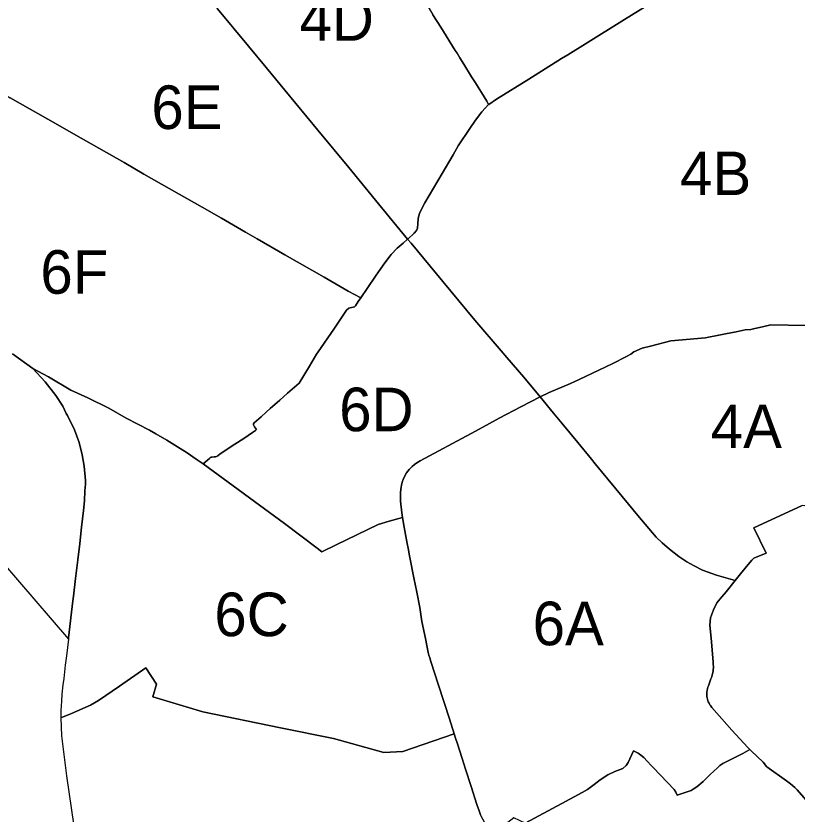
# Model space of a CAD drawing. Extents: x 152750 to 166250, y 378996 to 390000.
# Drawn here: x 157492 to 161080, y 382624 to 386288 of the extents above; entities that cross this region are included whole.
import ezdxf

# ---------------------------------------------------------------- set-up
doc = ezdxf.new("R2010")
doc.units = 0
doc.layers.add('BLT_Nummers', color=7, linetype='Continuous')
doc.layers.add('BLT_Shapes', color=7, linetype='Continuous')

msp = doc.modelspace()

# ---------------------------------------------------------------- linework, layer by layer
at = {"layer": 'BLT_Shapes'}
for p, q in [((158559.6, 386149.1), (158417.7, 386321.3)), ((159998.4, 386092.3), (160026.6, 386109.9)), ((159847.6, 385998.4), (159998.4, 386092.3)), ((159548.7, 386066.7), (159585, 386008.8)), ((159699.8, 385906.1), (159847.6, 385998.4)), ((159630.8, 385936.3), (159654.8, 385896.4)), ((159654.8, 385896.4), (159662.6, 385881.4)), ((159663.3, 385882.1), (159699.8, 385906.1)), ((159647.7, 385865.1), (159662.6, 385881.4)), ((159662.6, 385881.4), (159663.3, 385882.1)), ((159499.5, 385650), (159523.9, 385691.3)), ((159449.8, 385565.1), (159499.5, 385650)), ((159157.3, 385425.3), (159020.3, 385592.2)), ((159291.1, 385263.1), (159157.3, 385425.3)), ((159341.3, 385365.9), (159347.2, 385385.4)), ((159337.9, 385334.7), (159339.4, 385354.5)), ((159339.4, 385354.5), (159341.3, 385365.9)), ((159321.3, 385290.2), (159331.4, 385303.2)), ((159331.4, 385303.2), (159335.6, 385313.6)), ((159335.6, 385313.6), (159337.9, 385334.7)), ((159291.1, 385263.1), (159291.3, 385263.2)), ((159306.7, 385244.2), (159291.1, 385263.1)), ((159291.3, 385263.2), (159321.3, 385290.2)), ((159452, 385068.7), (159306.7, 385244.2)), ((158907.8, 385088.8), (158727.5, 385191.8)), ((159186.1, 385154.7), (159214.8, 385192.1)), ((159214.8, 385192.1), (159242.2, 385222.2)), ((159018.5, 385024.9), (158907.8, 385088.8)), ((159075.5, 384993.5), (159018.5, 385024.9)), ((159050.9, 384956.8), (159064, 384976.7)), ((159064, 384976.7), (159075.5, 384993.5)), ((159046.4, 384952.7), (159050.9, 384956.8)), ((160500.2, 384796.8), (160658.9, 384809.4)), ((160330.8, 384745.2), (160367.7, 384763.2)), ((157568.7, 384669.9), (157476.5, 384736.7)), ((158872.5, 384734.7), (158880.6, 384745.9)), ((159824.2, 384630.2), (159747, 384719.9)), ((157568.7, 384669.9), (157641, 384630.6)), ((157625.3, 384607.9), (157568.7, 384669.9)), ((157641, 384630.6), (157743.5, 384569.9)), ((159900, 384538.8), (159824.2, 384630.2)), ((160039.7, 384600.3), (160079.6, 384619)), ((157743.5, 384569.9), (157821.2, 384534.1)), ((158704.3, 384523.5), (158739.8, 384555.6)), ((159811.6, 384493.4), (159900, 384538.8)), ((159900, 384538.8), (159900.2, 384538.9)), ((157723, 384462.6), (157706.7, 384496.4)), ((158617.5, 384447.1), (158641.7, 384468.3)), ((158583, 384415.5), (158586.2, 384419.7)), ((158586.2, 384419.7), (158617.5, 384447.1)), ((157781.6, 384329), (157761, 384388.2)), ((158578.9, 384375.6), (158591.4, 384384)), ((158596.7, 384388.8), (158588.1, 384402.2)), ((158591.4, 384384), (158596.7, 384388.8)), ((158134.5, 384370.1), (158184.3, 384340.8)), ((158497.4, 384321.5), (158537.9, 384348.3)), ((158537.9, 384348.3), (158578.9, 384375.6)), ((158184.3, 384340.8), (158245.9, 384302.4)), ((158430.6, 384277), (158497.4, 384321.5)), ((158245.9, 384302.4), (158278, 384281.6)), ((158278, 384281.6), (158320.3, 384253.7)), ((158320.3, 384253.7), (158352.5, 384231.8)), ((158352.5, 384231.8), (158371.5, 384249.1)), ((158386.5, 384261.5), (158392.3, 384263)), ((159322.4, 384228.7), (159333, 384236.8)), ((158352.5, 384231.8), (158725.7, 383957.6)), ((159270.1, 384159.2), (159277.4, 384176.1)), ((159277.4, 384176.1), (159286.5, 384190.3)), ((157808.9, 384108.2), (157811.2, 384137.7)), ((157811.2, 384137.7), (157811.6, 384154.5)), ((159261.2, 384123.8), (159263, 384133.9)), ((159258.4, 384085.6), (159259, 384101.8)), ((159259, 384101.8), (159261.2, 384123.8)), ((159259, 384060.6), (159258.4, 384085.6)), ((160881.5, 383937.4), (161102.9, 384039.9)), ((159267.9, 383985.6), (159206.9, 383968.8)), ((159206.9, 383968.8), (159267.9, 383985.6)), ((159275.4, 383940.8), (159267.9, 383985.6)), ((160398.6, 383934.1), (160348.6, 383994.7)), ((158725.7, 383957.6), (158875.7, 383844)), ((160433.3, 383895.4), (160398.6, 383934.1)), ((160937.5, 383821.9), (160881.5, 383937.4)), ((158875.7, 383844), (158897.1, 383827.1)), ((159321, 383701), (159300.3, 383809)), ((160872.6, 383789.9), (160882, 383798)), ((160882, 383798), (160937.5, 383821.9)), ((160646.2, 383743.9), (160606.6, 383764)), ((160862.7, 383779.3), (160872.6, 383789.9)), ((160710.4, 383719.8), (160646.2, 383743.9)), ((159325.2, 383678.4), (159321, 383701)), ((160795.2, 383696.3), (160710.4, 383719.8)), ((160711.4, 383593.9), (160734.5, 383620.9)), ((159355.7, 383507.5), (159346.4, 383572.2)), ((159373.4, 383430.4), (159355.7, 383507.5)), ((159379.6, 383398.3), (159373.4, 383430.4)), ((159392.6, 383340.9), (159389.1, 383352.5)), ((159397.9, 383323.7), (159392.6, 383340.9)), ((159432.8, 383214.7), (159397.9, 383323.7)), ((158088.2, 383294.8), (158136.8, 383219.8)), ((158136.8, 383219.8), (158120.7, 383162.5)), ((160665.2, 383177.2), (160665.6, 383185.1)), ((160665.2, 383170.5), (160665.2, 383177.2)), ((158120.7, 383162.5), (158350.9, 383093.6)), ((160667.9, 383151.1), (160666.7, 383157.9)), ((160669.9, 383144.7), (160667.9, 383151.1)), ((160672.3, 383139.1), (160669.9, 383144.7)), ((159268.3, 382911.5), (159504.8, 382992)), ((160868.5, 382914.2), (160863.3, 382919.8)), ((159556.6, 382830.2), (159541.6, 382879)), ((160648.3, 382773.8), (160619.1, 382749)), ((160602.7, 382738.1), (160593.4, 382732.2)), ((160619.1, 382749), (160602.7, 382738.1)), ((161069.1, 382746.3), (161050.5, 382762))]:
    msp.add_line(p, q, dxfattribs=at)
for points in [[(158206.4, 386577.5), (158296.1, 386469.4), (158417.7, 386321.3), (158559.6, 386149.1), (158640.6, 386051.2), (158726.9, 385947.1), (158878.9, 385763.5), (159020.3, 385592.2), (159157.3, 385425.3), (159291.1, 385263.1)], [(160613.2, 386488.3), (160580.8, 386461.3), (160520.7, 386417.7), (160286.8, 386271.8), (160108.2, 386160.3), (160026.6, 386109.9), (159998.4, 386092.3), (159847.6, 385998.4), (159699.8, 385906.1), (159663.3, 385882.1), (159662.6, 385881.4)], [(160286.8, 386271.8), (160520.7, 386417.7), (160580.8, 386461.3), (160613.2, 386488.3)], [(159299.6, 386466.5), (159339, 386403.1), (159389.6, 386322.5), (159407.4, 386293.5), (159442.8, 386236.3), (159509.8, 386129.4), (159517.9, 386116.7)], [(159662.6, 385881.4), (159654.8, 385896.4), (159630.8, 385936.3), (159614.8, 385961), (159602.5, 385980.9), (159585, 386008.8), (159548.7, 386066.7), (159530.9, 386095.3), (159517.9, 386116.7), (159509.8, 386129.4), (159442.8, 386236.3), (159407.4, 386293.5)], [(160026.6, 386109.9), (160108.2, 386160.3), (160286.8, 386271.8)], [(158726.9, 385947.1), (158640.6, 386051.2), (158559.6, 386149.1)], [(159517.9, 386116.7), (159530.9, 386095.3), (159548.7, 386066.7)], [(157147.5, 386096.8), (157264.2, 386027.4), (157403.9, 385947.6), (157465.3, 385912.5), (157684.2, 385787.5), (157756.2, 385746.7), (157988.5, 385614.5), (158079.9, 385562), (158276, 385450.2), (158347.1, 385409.7), (158435.6, 385358.9), (158545.8, 385295.9), (158599.5, 385264.6), (158727.5, 385191.8), (158907.8, 385088.8), (159018.5, 385024.9), (159075.5, 384993.5)], [(159585, 386008.8), (159602.5, 385980.9), (159614.8, 385961), (159630.8, 385936.3)], [(159020.3, 385592.2), (158878.9, 385763.5), (158726.9, 385947.1)], [(157756.2, 385746.7), (157684.2, 385787.5), (157465.3, 385912.5)], [(159662.6, 385881.4), (159647.7, 385865.1), (159631.4, 385847.3), (159602.5, 385809.6), (159576.2, 385771.2), (159523.9, 385691.3), (159499.5, 385650), (159449.8, 385565.1), (159370.6, 385429.9), (159347.2, 385385.4), (159341.3, 385365.9), (159339.4, 385354.5), (159337.9, 385334.7), (159335.6, 385313.6), (159331.4, 385303.2), (159321.3, 385290.2), (159291.3, 385263.2), (159291.1, 385263.1)], [(159523.9, 385691.3), (159576.2, 385771.2), (159602.5, 385809.6), (159631.4, 385847.3), (159647.7, 385865.1)], [(158276, 385450.2), (158079.9, 385562), (157988.5, 385614.5), (157756.2, 385746.7)], [(159347.2, 385385.4), (159370.6, 385429.9), (159449.8, 385565.1)], [(158435.6, 385358.9), (158347.1, 385409.7), (158276, 385450.2)], [(158727.5, 385191.8), (158599.5, 385264.6), (158545.8, 385295.9), (158435.6, 385358.9)], [(159291.1, 385263.1), (159269.8, 385245.1), (159242.2, 385222.2), (159214.8, 385192.1), (159186.1, 385154.7), (159146.5, 385097.5), (159104.7, 385036.4), (159075.5, 384993.5)], [(159242.2, 385222.2), (159269.8, 385245.1), (159291.1, 385263.1)], [(159291.1, 385263.1), (159306.7, 385244.2), (159452, 385068.7), (159599.6, 384891.3), (159720.3, 384751.2), (159747, 384719.9), (159824.2, 384630.2), (159900, 384538.8)], [(159075.5, 384993.5), (159104.7, 385036.4), (159146.5, 385097.5), (159186.1, 385154.7)], [(159747, 384719.9), (159720.3, 384751.2), (159599.6, 384891.3), (159452, 385068.7)], [(159075.5, 384993.5), (159064, 384976.7), (159050.9, 384956.8), (159046.4, 384952.7), (159027.4, 384947.6), (159020.5, 384946), (159010.8, 384937.3), (159003.6, 384928.1), (158951.4, 384850.5), (158880.6, 384745.9), (158872.5, 384734.7), (158839.9, 384680.1), (158792.8, 384602.5), (158739.8, 384555.6), (158704.3, 384523.5), (158660.1, 384485), (158641.7, 384468.3), (158617.5, 384447.1), (158586.2, 384419.7), (158583, 384415.5), (158582.8, 384410.8), (158588.1, 384402.2), (158596.7, 384388.8), (158591.4, 384384), (158578.9, 384375.6), (158537.9, 384348.3), (158497.4, 384321.5), (158430.6, 384277), (158418.6, 384268), (158413.2, 384265.2), (158407.7, 384264.3), (158401.7, 384263.4), (158392.3, 384263), (158386.5, 384261.5), (158381.8, 384258.3), (158371.5, 384249.1), (158352.5, 384231.8)], [(158880.6, 384745.9), (158951.4, 384850.5), (159003.6, 384928.1), (159010.8, 384937.3), (159020.5, 384946)], [(159020.5, 384946), (159027.4, 384947.6), (159046.4, 384952.7)], [(161120.2, 384867.2), (160958.7, 384869.5), (160952.6, 384868.2), (160907.9, 384858.1), (160886.6, 384852.9), (160867.1, 384848.9), (160841.6, 384847.2), (160800.8, 384838), (160751.9, 384828.9), (160704.6, 384818.6), (160673.7, 384812.5), (160658.9, 384809.4), (160500.2, 384796.8), (160406.1, 384772.5), (160367.7, 384763.2), (160330.8, 384745.2), (160316.1, 384735.1), (160294.1, 384722.4), (160234.2, 384692.6), (160168.6, 384661), (160079.6, 384619), (160039.7, 384600.3), (159941.4, 384558.4), (159900.2, 384538.9), (159900, 384538.8)], [(160886.6, 384852.9), (160907.9, 384858.1), (160952.6, 384868.2), (160958.7, 384869.5), (161120.2, 384867.2), (161149.4, 384865.5)], [(160704.6, 384818.6), (160751.9, 384828.9), (160800.8, 384838)], [(160800.8, 384838), (160841.6, 384847.2), (160867.1, 384848.9), (160886.6, 384852.9)], [(160367.7, 384763.2), (160406.1, 384772.5), (160500.2, 384796.8)], [(160658.9, 384809.4), (160673.7, 384812.5), (160704.6, 384818.6)], [(157476.5, 384736.7), (157568.7, 384669.9)], [(158739.8, 384555.6), (158792.8, 384602.5), (158839.9, 384680.1), (158872.5, 384734.7)], [(160079.6, 384619), (160168.6, 384661), (160234.2, 384692.6), (160294.1, 384722.4), (160316.1, 384735.1), (160330.8, 384745.2)], [(158352.5, 384231.8), (158320.3, 384253.7), (158278, 384281.6), (158245.9, 384302.4), (158184.3, 384340.8), (158134.5, 384370.1), (158105.5, 384386.4), (157997.9, 384441.2), (157918, 384487), (157821.2, 384534.1), (157743.5, 384569.9), (157641, 384630.6), (157568.7, 384669.9)], [(157568.7, 384669.9), (157625.3, 384607.9), (157674.4, 384546.1), (157706.7, 384496.4), (157723, 384462.6), (157728, 384453.4), (157761, 384388.2), (157781.6, 384329), (157796.2, 384273.2), (157805.4, 384220.4), (157811.6, 384154.5), (157811.2, 384137.7), (157808.9, 384108.2), (157805.9, 384062.1), (157801.7, 384017.2), (157797.8, 383979.3), (157793.6, 383940.2), (157784.9, 383865.4), (157776.3, 383791.2), (157765.7, 383705.3), (157755.9, 383624.1), (157753.4, 383602.6), (157733.6, 383433.2), (157732.8, 383426.7)], [(157706.7, 384496.4), (157674.4, 384546.1), (157625.3, 384607.9)], [(159900.2, 384538.9), (159941.4, 384558.4), (160039.7, 384600.3)], [(157821.2, 384534.1), (157918, 384487), (157997.9, 384441.2)], [(159900, 384538.8), (159811.6, 384493.4), (159711.9, 384440.8), (159653, 384409.5), (159582.5, 384371.3), (159348, 384245.4), (159333, 384236.8), (159322.4, 384228.7), (159312.3, 384219.9), (159297.6, 384205.5), (159286.5, 384190.3), (159277.4, 384176.1), (159270.1, 384159.2), (159266.3, 384148.1), (159263, 384133.9), (159261.2, 384123.8), (159259, 384101.8), (159258.4, 384085.6), (159259, 384060.6), (159264.3, 384007.3), (159267.9, 383985.6)], [(159900, 384538.8), (159961.6, 384464.6), (159998.9, 384418.8), (160072.1, 384329.8), (160135.2, 384253.5), (160152.7, 384231.6), (160305.6, 384046.9), (160348.6, 383994.7), (160398.6, 383934.1), (160433.3, 383895.4), (160459.5, 383869.5), (160493.8, 383839.6), (160536.2, 383806.7), (160573.7, 383782.3), (160606.6, 383764), (160646.2, 383743.9), (160710.4, 383719.8), (160795.2, 383696.3)], [(159998.9, 384418.8), (159961.6, 384464.6), (159900, 384538.8)], [(158641.7, 384468.3), (158660.1, 384485), (158704.3, 384523.5)], [(159582.5, 384371.3), (159653, 384409.5), (159711.9, 384440.8), (159811.6, 384493.4)], [(157761, 384388.2), (157728, 384453.4), (157723, 384462.6)], [(157997.9, 384441.2), (158105.5, 384386.4), (158134.5, 384370.1)], [(158588.1, 384402.2), (158582.8, 384410.8), (158583, 384415.5)], [(160135.2, 384253.5), (160072.1, 384329.8), (159998.9, 384418.8)], [(159333, 384236.8), (159348, 384245.4), (159582.5, 384371.3)], [(157811.6, 384154.5), (157805.4, 384220.4), (157796.2, 384273.2), (157781.6, 384329)], [(158392.3, 384263), (158401.7, 384263.4), (158407.7, 384264.3), (158413.2, 384265.2), (158418.6, 384268), (158430.6, 384277)], [(158371.5, 384249.1), (158381.8, 384258.3), (158386.5, 384261.5)], [(160348.6, 383994.7), (160305.6, 384046.9), (160152.7, 384231.6), (160135.2, 384253.5)], [(159206.9, 383968.8), (159155.5, 383952.7), (158962.9, 383859.8), (158897.1, 383827.1), (158875.7, 383844), (158725.7, 383957.6), (158352.5, 384231.8)], [(159286.5, 384190.3), (159297.6, 384205.5), (159312.3, 384219.9), (159322.4, 384228.7)], [(159263, 384133.9), (159266.3, 384148.1), (159270.1, 384159.2)], [(161492.7, 384141), (161232.4, 384136.5), (161220.8, 384025.3), (161102.9, 384039.9), (160881.5, 383937.4), (160937.5, 383821.9)], [(157801.7, 384017.2), (157805.9, 384062.1), (157808.9, 384108.2)], [(159267.9, 383985.6), (159264.3, 384007.3), (159259, 384060.6)], [(157793.6, 383940.2), (157797.8, 383979.3), (157801.7, 384017.2)], [(159267.9, 383985.6), (159275.4, 383940.8), (159289.5, 383865.2), (159293.6, 383843.7), (159300.3, 383809), (159321, 383701), (159325.2, 383678.4), (159333.5, 383642.2), (159346.4, 383572.2), (159355.7, 383507.5), (159373.4, 383430.4), (159379.6, 383398.3)], [(158897.1, 383827.1), (158962.9, 383859.8), (159155.5, 383952.7), (159206.9, 383968.8)], [(157776.3, 383791.2), (157784.9, 383865.4), (157793.6, 383940.2)], [(159300.3, 383809), (159293.6, 383843.7), (159289.5, 383865.2), (159275.4, 383940.8)], [(160493.8, 383839.6), (160459.5, 383869.5), (160433.3, 383895.4)], [(160606.6, 383764), (160573.7, 383782.3), (160536.2, 383806.7), (160493.8, 383839.6)], [(157397.8, 383816.1), (157498.7, 383699.6), (157732.8, 383426.7), (157723.2, 383349.5), (157718.2, 383307.9), (157711.3, 383246), (157707.4, 383216.4), (157703.2, 383174.8), (157700.5, 383141.4), (157697.9, 383099.2), (157697.9, 383065.1), (157701.5, 382982.9), (157724.5, 382799.2), (157778.7, 382420.6), (157721.2, 382367.1), (157633.4, 382451.6), (157531.2, 382505), (157333.5, 382604.9)], [(157397.8, 383816.1), (157498.7, 383699.6), (157732.8, 383426.7)], [(160937.5, 383821.9), (160882, 383798), (160872.6, 383789.9), (160862.7, 383779.3), (160819.5, 383726.8), (160795.2, 383696.3)], [(157755.9, 383624.1), (157765.7, 383705.3), (157776.3, 383791.2)], [(160795.2, 383696.3), (160819.5, 383726.8), (160862.7, 383779.3)], [(160795.2, 383696.3), (160753.8, 383644.3), (160734.5, 383620.9), (160711.4, 383593.9), (160695.6, 383561.8), (160682.7, 383525.3), (160678.5, 383491.5), (160685.8, 383431.4), (160694.3, 383322.7), (160695.1, 383311.9), (160696.4, 383300.1), (160694.2, 383283.3), (160692.4, 383272.1), (160690.4, 383262.6), (160688, 383253.5), (160684.5, 383244), (160679.2, 383230.3), (160672.5, 383212.6), (160669.8, 383205.5), (160667.9, 383199.5), (160666.5, 383190.5), (160665.6, 383185.1), (160665.2, 383177.2), (160665.2, 383170.5), (160665.6, 383164.1), (160666.7, 383157.9), (160667.9, 383151.1), (160669.9, 383144.7), (160672.3, 383139.1), (160675.4, 383132.1), (160679.4, 383125.2), (160681.9, 383121.4), (160688.5, 383112.2), (160780, 383008.5), (160853.9, 382929.9), (160863.3, 382919.8)], [(160734.5, 383620.9), (160753.8, 383644.3), (160795.2, 383696.3)], [(159346.4, 383572.2), (159333.5, 383642.2), (159325.2, 383678.4)], [(157732.8, 383426.7), (157733.6, 383433.2), (157753.4, 383602.6), (157755.9, 383624.1)], [(160682.7, 383525.3), (160695.6, 383561.8), (160711.4, 383593.9)], [(160694.3, 383322.7), (160685.8, 383431.4), (160678.5, 383491.5), (160682.7, 383525.3)], [(157732.8, 383426.7), (157723.2, 383349.5), (157718.2, 383307.9), (157711.3, 383246), (157707.4, 383216.4), (157703.2, 383174.8), (157700.5, 383141.4), (157697.9, 383099.2), (157697.9, 383065.1)], [(159379.6, 383398.3), (159386, 383364.7), (159389.1, 383352.5), (159392.6, 383340.9), (159397.9, 383323.7), (159432.8, 383214.7), (159482.6, 383060.8), (159504.8, 382992)], [(159389.1, 383352.5), (159386, 383364.7), (159379.6, 383398.3)], [(160694.2, 383283.3), (160696.4, 383300.1), (160695.1, 383311.9), (160694.3, 383322.7)], [(158136.8, 383219.8), (158088.2, 383294.8), (157967.5, 383211.1), (157870.3, 383145), (157833.5, 383122.9), (157746.9, 383084.7), (157697.9, 383065.1)], [(157833.5, 383122.9), (157870.3, 383145), (157967.5, 383211.1), (158088.2, 383294.8)], [(160672.5, 383212.6), (160679.2, 383230.3), (160684.5, 383244), (160688, 383253.5), (160690.4, 383262.6)], [(160690.4, 383262.6), (160692.4, 383272.1), (160694.2, 383283.3)], [(159504.8, 382992), (159268.3, 382911.5), (159182.2, 382906), (158949.9, 382970.7), (158707, 383019.1), (158350.9, 383093.6), (158120.7, 383162.5), (158136.8, 383219.8)], [(159504.8, 382992), (159482.6, 383060.8), (159432.8, 383214.7)], [(160665.6, 383185.1), (160666.5, 383190.5), (160667.9, 383199.5), (160669.8, 383205.5), (160672.5, 383212.6)], [(160666.7, 383157.9), (160665.6, 383164.1), (160665.2, 383170.5)], [(160688.5, 383112.2), (160681.9, 383121.4), (160679.4, 383125.2), (160675.4, 383132.1), (160672.3, 383139.1)], [(157697.9, 383065.1), (157746.9, 383084.7), (157833.5, 383122.9)], [(160863.3, 382919.8), (160853.9, 382929.9), (160780, 383008.5), (160688.5, 383112.2)], [(157697.9, 383065.1), (157701.5, 382982.9), (157724.5, 382799.2), (157778.7, 382420.6), (157721.2, 382367.1)], [(158350.9, 383093.6), (158707, 383019.1), (158949.9, 382970.7), (159182.2, 382906), (159268.3, 382911.5)], [(159504.8, 382992), (159511, 382972.8), (159520.3, 382945.8), (159529.5, 382917.4), (159541.6, 382879), (159556.6, 382830.2), (159582.3, 382750.4), (159608.9, 382667.3), (159611, 382662.3), (159617.8, 382642.5), (159626.4, 382620.6), (159635.5, 382601.1), (159646.7, 382578.7), (159661.8, 382553.5), (159676.3, 382526.1), (159685.1, 382513.6), (159690.4, 382506.6)], [(159541.6, 382879), (159529.5, 382917.4), (159520.3, 382945.8), (159511, 382972.8), (159504.8, 382992)], [(159830.6, 382582), (159998.9, 382672.5), (160092.3, 382722), (160117.8, 382735.9), (160148.5, 382759.2), (160176.2, 382780.1), (160211.2, 382803.8), (160243.3, 382819.1), (160279.1, 382833.3), (160295.5, 382846.1), (160303.4, 382860), (160329.3, 382913.7), (160350.1, 382903.4), (160362.5, 382894.3), (160375.6, 382882.6), (160390.9, 382865.8), (160411.4, 382845.8), (160420.6, 382835.9), (160515.9, 382737), (160522.5, 382724.9), (160529.7, 382709.6), (160593.4, 382732.2), (160602.7, 382738.1), (160619.1, 382749), (160648.3, 382773.8), (160680.4, 382804.9), (160714.2, 382835.9), (160725.5, 382846.1), (160739.7, 382855.3), (160830.6, 382901.6), (160863.3, 382919.8)], [(160863.3, 382919.8), (160830.6, 382901.6), (160739.7, 382855.3), (160725.5, 382846.1), (160714.2, 382835.9)], [(160863.3, 382919.8), (160868.5, 382914.2), (160924.2, 382861.3), (160939.9, 382842.1), (160941.3, 382841), (161030.8, 382775.7), (161050.5, 382762), (161069.1, 382746.3), (161079.7, 382735.3), (161121.2, 382688.1)], [(160390.9, 382865.8), (160375.6, 382882.6), (160362.5, 382894.3), (160350.1, 382903.4), (160329.3, 382913.7), (160303.4, 382860), (160295.5, 382846.1), (160279.1, 382833.3)], [(161050.5, 382762), (161030.8, 382775.7), (160941.3, 382841), (160939.9, 382842.1), (160924.2, 382861.3), (160868.5, 382914.2)], [(160420.6, 382835.9), (160411.4, 382845.8), (160390.9, 382865.8)], [(159617.8, 382642.5), (159611, 382662.3), (159608.9, 382667.3), (159582.3, 382750.4), (159556.6, 382830.2)], [(160279.1, 382833.3), (160243.3, 382819.1), (160211.2, 382803.8)], [(160522.5, 382724.9), (160515.9, 382737), (160420.6, 382835.9)], [(160714.2, 382835.9), (160680.4, 382804.9), (160648.3, 382773.8)], [(160211.2, 382803.8), (160176.2, 382780.1), (160148.5, 382759.2)], [(160148.5, 382759.2), (160117.8, 382735.9), (160092.3, 382722), (159998.9, 382672.5), (159830.6, 382582), (159778.4, 382606.8), (159730.6, 382568.3), (159744.6, 382535.7)], [(161121.2, 382688.1), (161079.7, 382735.3), (161069.1, 382746.3)], [(160593.4, 382732.2), (160529.7, 382709.6), (160522.5, 382724.9)], [(159635.5, 382601.1), (159626.4, 382620.6), (159617.8, 382642.5)]]:
    msp.add_lwpolyline(points, dxfattribs=at)

# ---------------------------------------------------------------- texts
at = {"layer": 'BLT_Nummers'}
for s, p in [('4D', (158794.3, 386174)), ('6E', (158113.8, 385769)), ('4B', (160542.3, 385465.3)), ('6F', (157604, 385012.6)), ('6D', (158976.6, 384381.4)), ('4A', (160683.5, 384303.9)), ('6C', (158403.2, 383440.4)), ('6A', (159865.3, 383398.7))]:
    msp.add_text(s, height=200, dxfattribs=at).set_placement(p)

doc.saveas('drawing.dxf')
